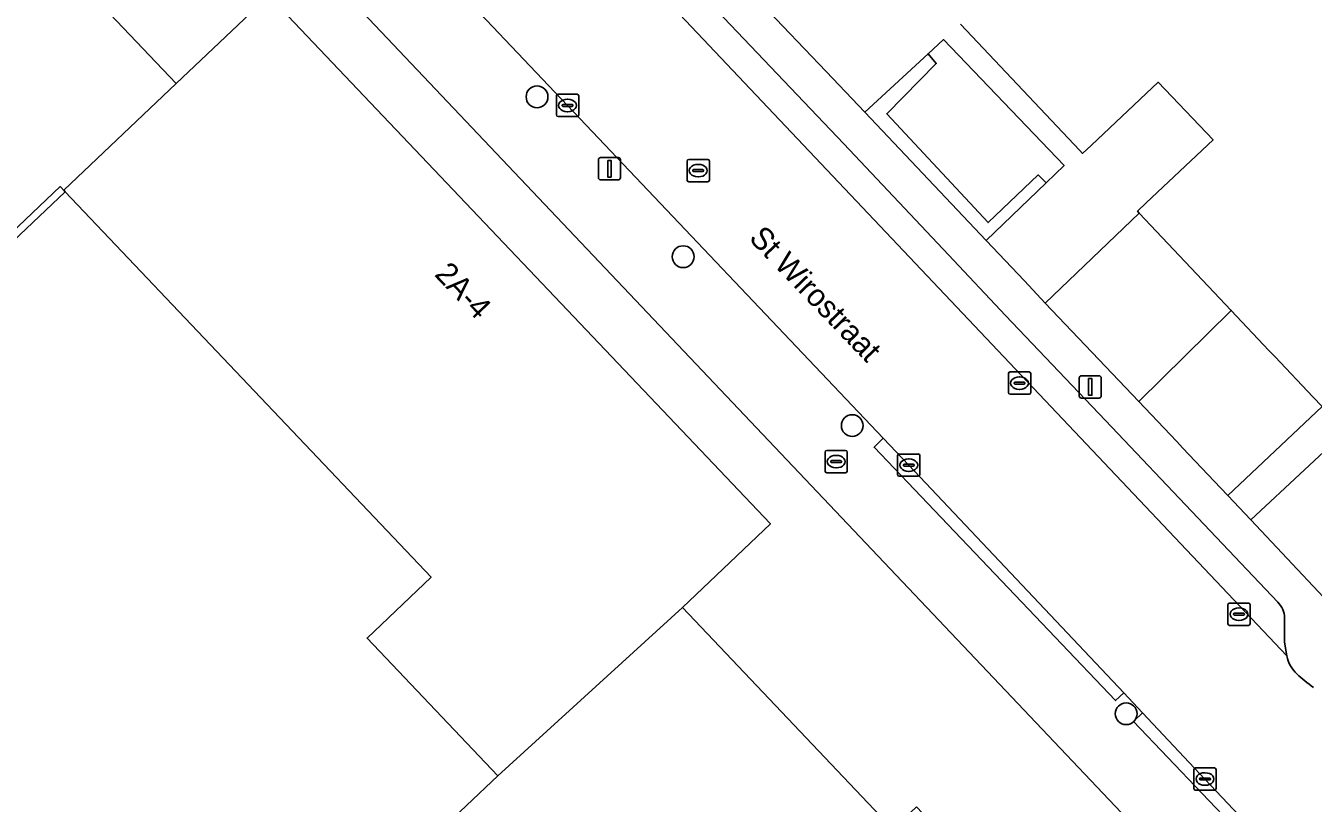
# Model space of a CAD drawing. Extents: x 162523 to 163266, y 381230 to 382050.
# Drawn here: x 163097.3 to 163155, y 381450.2 to 381485 of the extents above; entities that cross this region are included whole.
import ezdxf

# ---------------------------------------------------------------- set-up
doc = ezdxf.new("R2010")
doc.units = 0
for name, color, linetype in [('IMGEO_Boom', 7, 'Continuous'), ('IMGEO_Brandkraan', 7, 'Continuous'), ('IMGEO_Erf', 7, 'Continuous'), ('IMGEO_Groenvoorziening', 7, 'Continuous'), ('IMGEO_Haag', 7, 'Continuous'), ('IMGEO_Kolk', 7, 'Continuous'), ('IMGEO_Lichtmast', 7, 'Continuous'), ('IMGEO_Muur', 7, 'Continuous'), ('IMGEO_Openbare_ruimte_label', 7, 'Continuous'), ('IMGEO_Pand', 7, 'Continuous'), ('IMGEO_Pand_nummerreeks', 7, 'Continuous'), ('IMGEO_Parkeervlak_open', 7, 'Continuous'), ('IMGEO_Rijbaan_lokaal_open', 7, 'Continuous'), ('IMGEO_Rioolput', 7, 'Continuous'), ('IMGEO_Struiken', 7, 'Continuous'), ('IMGEO_Voetpad_open', 7, 'Continuous')]:
    doc.layers.add(name, color=color, linetype=linetype)

msp = doc.modelspace()

# ---------------------------------------------------------------- linework, layer by layer
at = {"layer": 'IMGEO_Boom'}
for centre in [(163120.198, 381481.847), (163126.757, 381474.673), (163134.343, 381467.094), (163146.635, 381454.168)]:
    msp.add_circle(centre, 0.489, dxfattribs=at)
at = {"layer": 'IMGEO_Brandkraan'}
for p, q in [((163133.196, 381465.979), (163134.048, 381465.979)), ((163133.121, 381465.053), (163133.121, 381465.905)), ((163133.38, 381465.473), (163133.38, 381465.485)), ((163133.818, 381465.436), (163133.42, 381465.436)), ((163133.423, 381465.522), (163133.821, 381465.522)), ((163133.609, 381465.759), (163133.634, 381465.759)), ((163133.864, 381465.485), (163133.864, 381465.473)), ((163134.122, 381465.905), (163134.122, 381465.053)), ((163134.048, 381464.979), (163133.196, 381464.979)), ((163133.632, 381465.199), (163133.607, 381465.199))]:
    msp.add_line(p, q, dxfattribs=at)
for points in [[(163133.196, 381465.979), (163134.048, 381465.979)], [(163133.121, 381465.053), (163133.121, 381465.905)], [(163134.122, 381465.905), (163134.122, 381465.053)], [(163134.048, 381464.979), (163133.196, 381464.979)]]:
    msp.add_lwpolyline(points, dxfattribs=at)
for centre, radius, start, end in [((163133.198, 381465.903), 0.0765, 91.55205, 178.44795), ((163133.198, 381465.903), 0.0765, 91.55205, 178.44795), ((163134.046, 381465.903), 0.0765, 1.55205, 88.44795), ((163134.046, 381465.903), 0.0765, 1.55205, 88.44795), ((163133.42, 381465.482), 0.0403, 85.87752, 175.75265), ((163133.417, 381465.472), 0.0366, 178.93798, 274.71019), ((163133.821, 381465.479), 0.043, 264.86636, 352.45326), ((163133.825, 381465.484), 0.0386, 1.73085, 96.63898), ((163133.198, 381465.055), 0.0765, 181.55205, 268.44795), ((163133.198, 381465.055), 0.0765, 181.55205, 268.44795), ((163134.046, 381465.055), 0.0765, 271.55205, 358.44795), ((163134.046, 381465.055), 0.0765, 271.55205, 358.44795)]:
    msp.add_arc(centre, radius, start, end, dxfattribs=at)
for centre, major_axis, ratio, start_param, end_param in [((163133.608, 381465.479), (-0.387, 0.002), 0.722429, 4.712389, 7.853982), ((163133.633, 381465.479), (-0.39, 0.002), 0.717154, 1.570796, 4.712389)]:
    msp.add_ellipse(centre, major_axis=major_axis, ratio=ratio, start_param=start_param, end_param=end_param, dxfattribs=at)
at = {"layer": 'IMGEO_Erf'}
for points in [[(163164.14, 381431.046), (163132.502, 381464.414), (163084.908, 381514.61)], [(163114.481, 381447.632), (163118.435, 381451.383), (163112.57, 381457.562), (163115.448, 381460.293), (163099.031, 381477.589), (163098.961, 381477.663), (163104.001, 381482.447), (163098.348, 381488.402), (163102.509, 381492.351), (163108.162, 381486.396), (163130.674, 381462.68), (163126.725, 381458.93), (163136.166, 381448.983)], [(163129.505, 381486.843), (163131.231, 381485.018), (163133.175, 381482.974), (163134.903, 381481.158), (163137.748, 381483.775), (163138.443, 381484.414), (163143.851, 381478.767), (163143.043, 381477.989), (163140.348, 381475.4), (163142.071, 381473.594), (163143.001, 381472.593), (163147.22, 381476.63), (163147.144, 381476.711), (163147.526, 381477.095), (163150.533, 381479.91), (163148.073, 381482.5), (163145.074, 381479.679), (163144.682, 381479.309), (163144.553, 381479.441), (163139.198, 381485.108)]]:
    msp.add_lwpolyline(points, dxfattribs=at)
for points in [[(163099.031, 381477.589), (163094.073, 381472.905), (163093.088, 381473.918), (163093.323, 381474.159), (163094.084, 381473.354), (163098.799, 381477.819)], [(163155.423, 381467.948), (163155.005, 381468.39), (163153.321, 381470.173), (163153.044, 381470.465), (163151.347, 381472.262), (163147.197, 381468.169), (163148.891, 381466.399), (163149.177, 381466.081), (163150.867, 381464.308), (163151.191, 381463.963)]]:
    msp.add_lwpolyline(points, close=True, dxfattribs=at)
at = {"layer": 'IMGEO_Groenvoorziening'}
for points in [[(163138.443, 381484.414), (163137.748, 381483.775), (163138.11, 381483.34), (163135.891, 381481.086), (163140.437, 381476.204), (163142.691, 381478.34), (163143.043, 381477.989), (163143.851, 381478.767)], [(163137.748, 381483.775), (163134.903, 381481.158), (163140.348, 381475.4), (163143.043, 381477.989), (163142.691, 381478.34), (163140.437, 381476.204), (163135.891, 381481.086), (163138.11, 381483.34)], [(163147.197, 381468.169), (163151.347, 381472.262), (163147.22, 381476.63), (163143.001, 381472.593)]]:
    msp.add_lwpolyline(points, close=True, dxfattribs=at)
at = {"layer": 'IMGEO_Haag'}
for points in [[(163134.903, 381481.158), (163140.348, 381475.4), (163143.043, 381477.989), (163142.691, 381478.34), (163140.437, 381476.204), (163135.891, 381481.086), (163138.11, 381483.34), (163137.748, 381483.775)], [(163147.197, 381468.169), (163151.347, 381472.262), (163147.22, 381476.63), (163143.001, 381472.593)]]:
    msp.add_lwpolyline(points, close=True, dxfattribs=at)
at = {"layer": 'IMGEO_Kolk'}
for p, q in [((163121.068, 381481.032), (163121.068, 381481.884)), ((163121.143, 381481.958), (163121.995, 381481.958)), ((163121.556, 381481.738), (163121.581, 381481.738)), ((163122.069, 381481.884), (163122.069, 381481.032)), ((163121.327, 381481.452), (163121.327, 381481.464)), ((163121.765, 381481.415), (163121.367, 381481.415)), ((163121.37, 381481.501), (163121.768, 381481.501)), ((163121.579, 381481.178), (163121.554, 381481.178)), ((163121.811, 381481.464), (163121.811, 381481.452)), ((163121.995, 381480.958), (163121.143, 381480.958)), ((163141.349, 381468.574), (163141.349, 381469.426)), ((163141.424, 381469.5), (163142.276, 381469.5)), ((163142.35, 381469.426), (163142.35, 381468.574)), ((163141.608, 381468.994), (163141.608, 381469.006)), ((163142.046, 381468.957), (163141.648, 381468.957)), ((163141.651, 381469.043), (163142.049, 381469.043)), ((163141.837, 381469.28), (163141.862, 381469.28)), ((163142.092, 381469.006), (163142.092, 381468.994)), ((163142.276, 381468.5), (163141.424, 381468.5)), ((163141.86, 381468.72), (163141.835, 381468.72)), ((163136.381, 381464.894), (163136.381, 381465.746)), ((163136.456, 381465.82), (163137.308, 381465.82)), ((163136.683, 381465.363), (163137.081, 381465.363)), ((163136.869, 381465.6), (163136.894, 381465.6)), ((163137.382, 381465.746), (163137.382, 381464.894)), ((163137.308, 381464.82), (163136.456, 381464.82)), ((163136.64, 381465.314), (163136.64, 381465.326)), ((163137.078, 381465.277), (163136.68, 381465.277)), ((163136.892, 381465.04), (163136.867, 381465.04)), ((163137.124, 381465.326), (163137.124, 381465.314)), ((163151.197, 381458.206), (163151.197, 381459.058)), ((163151.272, 381459.132), (163152.124, 381459.132)), ((163152.198, 381459.058), (163152.198, 381458.206)), ((163151.456, 381458.626), (163151.456, 381458.638)), ((163151.894, 381458.589), (163151.496, 381458.589)), ((163151.499, 381458.675), (163151.897, 381458.675)), ((163151.685, 381458.912), (163151.71, 381458.912)), ((163151.94, 381458.638), (163151.94, 381458.626)), ((163152.124, 381458.132), (163151.272, 381458.132)), ((163151.708, 381458.352), (163151.683, 381458.352)), ((163149.672, 381450.812), (163149.672, 381451.664)), ((163149.747, 381451.738), (163150.599, 381451.738)), ((163150.16, 381451.518), (163150.185, 381451.518)), ((163150.673, 381451.664), (163150.673, 381450.812)), ((163149.931, 381451.232), (163149.931, 381451.244)), ((163150.369, 381451.195), (163149.971, 381451.195)), ((163149.974, 381451.281), (163150.372, 381451.281)), ((163150.183, 381450.958), (163150.158, 381450.958)), ((163150.415, 381451.244), (163150.415, 381451.232)), ((163150.599, 381450.738), (163149.747, 381450.738))]:
    msp.add_line(p, q, dxfattribs=at)
for points in [[(163121.068, 381481.032), (163121.068, 381481.884)], [(163121.143, 381481.958), (163121.995, 381481.958)], [(163122.069, 381481.884), (163122.069, 381481.032)], [(163121.995, 381480.958), (163121.143, 381480.958)], [(163141.349, 381468.574), (163141.349, 381469.426)], [(163141.424, 381469.5), (163142.276, 381469.5)], [(163142.35, 381469.426), (163142.35, 381468.574)], [(163142.276, 381468.5), (163141.424, 381468.5)], [(163136.381, 381464.894), (163136.381, 381465.746)], [(163136.456, 381465.82), (163137.308, 381465.82)], [(163137.382, 381465.746), (163137.382, 381464.894)], [(163137.308, 381464.82), (163136.456, 381464.82)], [(163151.197, 381458.206), (163151.197, 381459.058)], [(163151.272, 381459.132), (163152.124, 381459.132)], [(163152.198, 381459.058), (163152.198, 381458.206)], [(163152.124, 381458.132), (163151.272, 381458.132)], [(163149.672, 381450.812), (163149.672, 381451.664)], [(163149.747, 381451.738), (163150.599, 381451.738)], [(163150.673, 381451.664), (163150.673, 381450.812)], [(163150.599, 381450.738), (163149.747, 381450.738)]]:
    msp.add_lwpolyline(points, dxfattribs=at)
for centre, radius, start, end in [((163121.145, 381481.882), 0.0765, 91.55205, 178.44795), ((163121.145, 381481.882), 0.0765, 91.55205, 178.44795), ((163121.993, 381481.882), 0.0765, 1.55205, 88.44795), ((163121.993, 381481.882), 0.0765, 1.55205, 88.44795), ((163121.145, 381481.034), 0.0765, 181.55205, 268.44795), ((163121.145, 381481.034), 0.0765, 181.55205, 268.44795), ((163121.367, 381481.461), 0.0403, 85.87752, 175.75265), ((163121.364, 381481.451), 0.0366, 178.93798, 274.71019), ((163121.768, 381481.458), 0.043, 264.86636, 352.45326), ((163121.772, 381481.463), 0.0386, 1.73085, 96.63898), ((163121.993, 381481.034), 0.0765, 271.55205, 358.44795), ((163121.993, 381481.034), 0.0765, 271.55205, 358.44795), ((163141.426, 381469.424), 0.0765, 91.55205, 178.44795), ((163141.426, 381469.424), 0.0765, 91.55205, 178.44795), ((163142.274, 381469.424), 0.0765, 1.55205, 88.44795), ((163142.274, 381469.424), 0.0765, 1.55205, 88.44795), ((163141.648, 381469.003), 0.0403, 85.87752, 175.75265), ((163141.645, 381468.993), 0.0366, 178.93798, 274.71019), ((163142.049, 381469), 0.043, 264.86636, 352.45326), ((163142.053, 381469.005), 0.0386, 1.73085, 96.63898), ((163141.426, 381468.576), 0.0765, 181.55205, 268.44795), ((163141.426, 381468.576), 0.0765, 181.55205, 268.44795), ((163142.274, 381468.576), 0.0765, 271.55205, 358.44795), ((163142.274, 381468.576), 0.0765, 271.55205, 358.44795), ((163136.458, 381465.744), 0.0765, 91.55205, 178.44795), ((163136.458, 381465.744), 0.0765, 91.55205, 178.44795), ((163136.68, 381465.323), 0.0403, 85.87752, 175.75265), ((163137.085, 381465.325), 0.0386, 1.73085, 96.63898), ((163137.306, 381465.744), 0.0765, 1.55205, 88.44795), ((163137.306, 381465.744), 0.0765, 1.55205, 88.44795), ((163136.458, 381464.896), 0.0765, 181.55205, 268.44795), ((163136.458, 381464.896), 0.0765, 181.55205, 268.44795), ((163136.677, 381465.313), 0.0366, 178.93798, 274.71019), ((163137.081, 381465.32), 0.043, 264.86636, 352.45326), ((163137.306, 381464.896), 0.0765, 271.55205, 358.44795), ((163137.306, 381464.896), 0.0765, 271.55205, 358.44795), ((163151.274, 381459.056), 0.0765, 91.55205, 178.44795), ((163151.274, 381459.056), 0.0765, 91.55205, 178.44795), ((163152.122, 381459.056), 0.0765, 1.55205, 88.44795), ((163152.122, 381459.056), 0.0765, 1.55205, 88.44795), ((163151.496, 381458.635), 0.0403, 85.87752, 175.75265), ((163151.493, 381458.625), 0.0366, 178.93798, 274.71019), ((163151.897, 381458.632), 0.043, 264.86636, 352.45326), ((163151.901, 381458.637), 0.0386, 1.73085, 96.63898), ((163151.274, 381458.208), 0.0765, 181.55205, 268.44795), ((163151.274, 381458.208), 0.0765, 181.55205, 268.44795), ((163152.122, 381458.208), 0.0765, 271.55205, 358.44795), ((163152.122, 381458.208), 0.0765, 271.55205, 358.44795), ((163149.749, 381451.662), 0.0765, 91.55205, 178.44795), ((163149.749, 381451.662), 0.0765, 91.55205, 178.44795), ((163150.597, 381451.662), 0.0765, 1.55205, 88.44795), ((163150.597, 381451.662), 0.0765, 1.55205, 88.44795), ((163149.971, 381451.241), 0.0403, 85.87752, 175.75265), ((163149.968, 381451.231), 0.0366, 178.93798, 274.71019), ((163150.372, 381451.238), 0.043, 264.86636, 352.45326), ((163150.376, 381451.243), 0.0386, 1.73085, 96.63898), ((163149.749, 381450.814), 0.0765, 181.55205, 268.44795), ((163149.749, 381450.814), 0.0765, 181.55205, 268.44795), ((163150.597, 381450.814), 0.0765, 271.55205, 358.44795), ((163150.597, 381450.814), 0.0765, 271.55205, 358.44795)]:
    msp.add_arc(centre, radius, start, end, dxfattribs=at)
for centre, major_axis, ratio, start_param, end_param in [((163121.555, 381481.458), (-0.387, 0.002), 0.722429, 4.712389, 7.853982), ((163121.58, 381481.458), (-0.39, 0.002), 0.717154, 1.570796, 4.712389), ((163141.836, 381469), (-0.387, 0.002), 0.722429, 4.712389, 7.853982), ((163141.861, 381469), (-0.39, 0.002), 0.717154, 1.570796, 4.712389), ((163136.868, 381465.32), (-0.387, 0.002), 0.722429, 4.712389, 7.853982), ((163136.893, 381465.32), (-0.39, 0.002), 0.717154, 1.570796, 4.712389), ((163151.684, 381458.632), (-0.387, 0.002), 0.722429, 4.712389, 7.853982), ((163151.709, 381458.632), (-0.39, 0.002), 0.717154, 1.570796, 4.712389), ((163150.159, 381451.238), (-0.387, 0.002), 0.722429, 4.712389, 7.853982), ((163150.184, 381451.238), (-0.39, 0.002), 0.717154, 1.570796, 4.712389)]:
    msp.add_ellipse(centre, major_axis=major_axis, ratio=ratio, start_param=start_param, end_param=end_param, dxfattribs=at)
at = {"layer": 'IMGEO_Lichtmast'}
for p, q in [((163122.953, 381478.219), (163122.953, 381479.019)), ((163122.953, 381479.019), (163122.953, 381478.219)), ((163123.053, 381479.119), (163123.843, 381479.119)), ((163123.843, 381479.119), (163123.053, 381479.119)), ((163123.943, 381479.019), (163123.943, 381478.219)), ((163123.943, 381478.219), (163123.943, 381479.019)), ((163123.843, 381478.119), (163123.053, 381478.119)), ((163123.053, 381478.119), (163123.843, 381478.119)), ((163144.527, 381468.431), (163144.527, 381469.231)), ((163144.527, 381469.231), (163144.527, 381468.431)), ((163144.627, 381469.331), (163145.417, 381469.331)), ((163145.417, 381469.331), (163144.627, 381469.331)), ((163145.517, 381469.231), (163145.517, 381468.431)), ((163145.517, 381468.431), (163145.517, 381469.231)), ((163145.417, 381468.331), (163144.627, 381468.331)), ((163144.627, 381468.331), (163145.417, 381468.331))]:
    msp.add_line(p, q, dxfattribs=at)
for points in [[(163123.373, 381478.994), (163123.523, 381478.994), (163123.523, 381478.244), (163123.373, 381478.244), (163123.373, 381478.994)], [(163144.947, 381469.206), (163145.097, 381469.206), (163145.097, 381468.456), (163144.947, 381468.456), (163144.947, 381469.206)]]:
    msp.add_lwpolyline(points, dxfattribs=at)
for centre, start, end in [((163123.053, 381479.019), 90, 180), ((163123.053, 381479.019), 90, 180), ((163123.843, 381479.019), 0, 90), ((163123.843, 381479.019), 360, 90), ((163123.053, 381478.219), 180, 270), ((163123.053, 381478.219), 180, 270), ((163123.843, 381478.219), 270, 0), ((163123.843, 381478.219), 270, 0), ((163144.627, 381469.231), 90, 180), ((163144.627, 381469.231), 90, 180), ((163145.417, 381469.231), 0, 90), ((163145.417, 381469.231), 360, 90), ((163144.627, 381468.431), 180, 270), ((163144.627, 381468.431), 180, 270), ((163145.417, 381468.431), 270, 0), ((163145.417, 381468.431), 270, 0)]:
    msp.add_arc(centre, 0.1, start, end, dxfattribs=at)
at = {"layer": 'IMGEO_Muur'}
msp.add_lwpolyline([(163098.799, 381477.819), (163094.084, 381473.354), (163093.323, 381474.159), (163093.088, 381473.918), (163094.073, 381472.905), (163099.031, 381477.589)], close=True, dxfattribs=at)
at = {"layer": 'IMGEO_Pand'}
for points in [[(163098.348, 381488.402), (163104.001, 381482.447), (163108.162, 381486.396), (163102.509, 381492.351)], [(163108.162, 381486.396), (163104.001, 381482.447), (163098.961, 381477.663), (163099.031, 381477.589), (163115.448, 381460.293), (163112.57, 381457.562), (163118.435, 381451.383), (163126.725, 381458.93), (163130.674, 381462.68)], [(163137.233, 381449.996), (163136.166, 381448.983), (163126.725, 381458.93), (163118.435, 381451.383), (163114.481, 381447.632), (163123.738, 381437.856), (163129.571, 381443.229), (163131.108, 381441.63), (163132.037, 381442.601), (163137.174, 381437.201), (163134.409, 381434.587), (163133.447, 381435.604), (163129.452, 381431.821), (163133.99, 381427.03), (163138.433, 381422.338), (163151.71, 381434.837), (163150.856, 381435.729), (163150.524, 381436.076), (163150.431, 381436.019)]]:
    msp.add_lwpolyline(points, close=True, dxfattribs=at)
msp.add_lwpolyline([(163139.198, 381485.108), (163144.553, 381479.441), (163144.682, 381479.309), (163145.074, 381479.679), (163148.073, 381482.5), (163150.533, 381479.91), (163147.526, 381477.095), (163147.144, 381476.711), (163147.22, 381476.63), (163151.347, 381472.262), (163153.044, 381470.465), (163153.321, 381470.173), (163155.005, 381468.39), (163155.423, 381467.948)], dxfattribs=at)
at = {"layer": 'IMGEO_Parkeervlak_open'}
for points in [[(163103.568, 381509.88), (163153.839, 381456.764)], [(163133.961, 381479.729), (163128.284, 381485.708)], [(163138.664, 381474.76), (163133.961, 381479.729)], [(163141.227, 381472.04), (163138.664, 381474.76)], [(163145.704, 381467.321), (163141.227, 381472.04)], [(163149.855, 381462.952), (163145.704, 381467.321)], [(163153.441, 381459.174), (163149.855, 381462.952)], [(163153.739, 381457.379), (163153.742, 381458.462)], [(163153.839, 381456.764), (163153.739, 381457.379)]]:
    msp.add_lwpolyline(points, dxfattribs=at)
msp.add_arc((163152.701, 381458.441), 1.041, 1.12874, 44.70395, dxfattribs=at)
at = {"layer": 'IMGEO_Rijbaan_lokaal_open'}
for points in [[(163076.974, 381528.282), (163079.513, 381525.79), (163086.854, 381518.075), (163086.997, 381517.925), (163089.162, 381515.65), (163103.975, 381500), (163105.324, 381498.575), (163121.57, 381481.459), (163135.737, 381466.525), (163136.881, 381465.319), (163146.524, 381455.102), (163147.369, 381454.206), (163150.172, 381451.237), (163155.025, 381446.086), (163166.031, 381434.407), (163170.413, 381429.933)], [(163153.839, 381456.764), (163103.568, 381509.88)]]:
    msp.add_lwpolyline(points, dxfattribs=at)
for centre, radius, start, end in [((163155.345, 381457.082), 1.539, 191.92745, 227.19645), ((163158.283, 381460.058), 5.721, 225.85242, 235.3994)]:
    msp.add_arc(centre, radius, start, end, dxfattribs=at)
at = {"layer": 'IMGEO_Rioolput'}
for p, q in [((163126.931, 381478.108), (163126.931, 381478.96)), ((163127.006, 381479.034), (163127.858, 381479.034)), ((163127.419, 381478.814), (163127.444, 381478.814)), ((163127.932, 381478.96), (163127.932, 381478.108)), ((163127.19, 381478.528), (163127.19, 381478.54)), ((163127.628, 381478.491), (163127.23, 381478.491)), ((163127.233, 381478.577), (163127.631, 381478.577)), ((163127.442, 381478.254), (163127.417, 381478.254)), ((163127.674, 381478.54), (163127.674, 381478.528)), ((163127.858, 381478.034), (163127.006, 381478.034))]:
    msp.add_line(p, q, dxfattribs=at)
for points in [[(163126.931, 381478.108), (163126.931, 381478.96)], [(163127.006, 381479.034), (163127.858, 381479.034)], [(163127.932, 381478.96), (163127.932, 381478.108)], [(163127.858, 381478.034), (163127.006, 381478.034)]]:
    msp.add_lwpolyline(points, dxfattribs=at)
for centre, radius, start, end in [((163127.008, 381478.958), 0.0765, 91.55205, 178.44795), ((163127.008, 381478.958), 0.0765, 91.55205, 178.44795), ((163127.856, 381478.958), 0.0765, 1.55205, 88.44795), ((163127.856, 381478.958), 0.0765, 1.55205, 88.44795), ((163127.008, 381478.11), 0.0765, 181.55205, 268.44795), ((163127.008, 381478.11), 0.0765, 181.55205, 268.44795), ((163127.23, 381478.537), 0.0403, 85.87752, 175.75265), ((163127.227, 381478.527), 0.0366, 178.93798, 274.71019), ((163127.631, 381478.534), 0.043, 264.86636, 352.45326), ((163127.635, 381478.539), 0.0386, 1.73085, 96.63898), ((163127.856, 381478.11), 0.0765, 271.55205, 358.44795), ((163127.856, 381478.11), 0.0765, 271.55205, 358.44795)]:
    msp.add_arc(centre, radius, start, end, dxfattribs=at)
for centre, major_axis, ratio, start_param, end_param in [((163127.418, 381478.534), (-0.387, 0.002), 0.722429, 4.712389, 7.853982), ((163127.443, 381478.534), (-0.39, 0.002), 0.717154, 1.570796, 4.712389)]:
    msp.add_ellipse(centre, major_axis=major_axis, ratio=ratio, start_param=start_param, end_param=end_param, dxfattribs=at)
at = {"layer": 'IMGEO_Struiken'}
msp.add_lwpolyline([(163159.693, 381464.822), (163159.451, 381469.601), (163152.234, 381462.871), (163155.497, 381459.392)], dxfattribs=at)
at = {"layer": 'IMGEO_Voetpad_open'}
for points in [[(163068.737, 381527.889), (163069.406, 381527.653), (163072.516, 381527.583), (163076.869, 381523.043), (163077.167, 381519.718), (163077.476, 381519.136), (163078.537, 381520.449), (163081.613, 381517.216), (163083.008, 381514.758), (163084.908, 381514.61), (163132.502, 381464.414), (163164.14, 381431.046)], [(163155.025, 381446.086), (163154.664, 381445.741), (163146.963, 381453.818), (163147.369, 381454.206), (163146.524, 381455.102), (163146.16, 381454.755), (163135.32, 381466.126), (163135.737, 381466.525), (163121.57, 381481.459), (163105.324, 381498.575), (163103.975, 381500), (163089.162, 381515.65), (163086.997, 381517.925), (163086.854, 381518.075), (163086.512, 381517.747), (163081.429, 381523.05), (163079.143, 381525.436), (163079.513, 381525.79), (163076.974, 381528.282)], [(163134.903, 381481.158), (163133.175, 381482.974), (163131.231, 381485.018), (163129.505, 381486.843), (163124.263, 381492.39), (163122.544, 381494.214), (163120.61, 381496.261), (163118.88, 381498.086), (163113.645, 381503.623), (163111.89, 381505.496), (163111.016, 381506.526), (163108.343, 381509.358), (163102.711, 381515.323)], [(163105.878, 381509.418), (163110.49, 381504.514), (163112.58, 381502.341), (163117.116, 381497.542), (163123.28, 381490.987), (163128.284, 381485.708), (163133.961, 381479.729), (163138.664, 381474.76), (163141.227, 381472.04), (163145.704, 381467.321), (163149.855, 381462.952), (163153.441, 381459.174)], [(163159.641, 381454.516), (163155.497, 381459.392), (163152.234, 381462.871), (163151.191, 381463.963), (163150.867, 381464.308), (163149.177, 381466.081), (163148.891, 381466.399), (163147.197, 381468.169), (163143.001, 381472.593), (163142.071, 381473.594), (163140.348, 381475.4), (163134.903, 381481.158)], [(163155.423, 381467.948), (163151.191, 381463.963), (163152.234, 381462.871), (163159.451, 381469.601)], [(163153.742, 381458.462), (163153.739, 381457.379), (163153.839, 381456.764)]]:
    msp.add_lwpolyline(points, dxfattribs=at)
for points in [[(163146.524, 381455.102), (163136.881, 381465.319), (163135.737, 381466.525), (163135.32, 381466.126), (163146.16, 381454.755)], [(163147.369, 381454.206), (163146.963, 381453.818), (163154.664, 381445.741), (163155.025, 381446.086), (163150.172, 381451.237)]]:
    msp.add_lwpolyline(points, close=True, dxfattribs=at)
for centre, radius, start, end in [((163152.701, 381458.441), 1.041, 1.12874, 44.70395), ((163155.345, 381457.082), 1.539, 191.92745, 227.19645), ((163158.283, 381460.058), 5.721, 225.85242, 235.3994)]:
    msp.add_arc(centre, radius, start, end, dxfattribs=at)

# ---------------------------------------------------------------- texts
at = {"layer": 'IMGEO_Openbare_ruimte_label'}
msp.add_text('St Wirostraat', height=1, rotation=313.78457, dxfattribs=at).set_placement((163129.663, 381475.46))
at = {"layer": 'IMGEO_Pand_nummerreeks'}
msp.add_text('2A-4', height=1, rotation=313.48156, dxfattribs=at).set_placement((163115.56, 381473.845))

doc.saveas('drawing.dxf')
